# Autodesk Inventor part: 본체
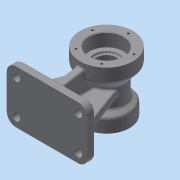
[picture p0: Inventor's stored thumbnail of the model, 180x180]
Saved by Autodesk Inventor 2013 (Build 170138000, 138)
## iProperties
Created: 2015-08
Part Number: 본체
Material: 일반
Document SubType Name: Modeling
Designer: Administrator
Density: 1 g/cm^3
Author: Administrator
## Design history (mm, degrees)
sketch "스케치3"
  geometry: L1 (0, 45)-(0, -45); L2 (0, 45)-(40, 45); L3 (40, 45)-(40, 25); L4 (26, 8.315)-(26, -19.804); L5 (26, -19.804)-(35, -25); L6 (35, -25)-(35, -45); L7 (35, -45)-(0, -45); L8 (26, 8.315)-(40, 25); 2 further points
  constraints: 16 end point, 3 parallel, 2 perpendicular, 1 coincident, 1 midpoint, 1 vertical
  dimensions: "d0" = 90 distance of L1.start L1.end; "d1" = 70 diameter of L6 L1; "d2" = 80 diameter of L3 L1; "d3" = 20 distance of L2.end L3.end; "d4" = 20 distance of L5.end L6.end; "d5" = 60 deg angle of L4 L5; "d6" = 40 deg angle of L4 L8; "d7" = 52 diameter of L4 L1
revolve "회전1" sketch "스케치3" stored, may be unused: angle "d8" = 90 deg
node "작업 평면1"
sketch "스케치8"
  geometry: L1 (61, -40)-(-61, -40); L2 (-61, -40)-(-61, 40); L3 (-61, 40)-(61, 40); L4 (61, 40)-(61, -40); L5 (61, -40)-(-61, 40); L6 (-61, -40)-(61, 40); 1 further point
  constraints: 12 end point, 2 midpoint, 2 parallel, 1 horizontal, 1 perpendicular
  dimensions: "d27" = 122 distance of L2.end L3.end; "d28" = 80 distance of L1.end L2.end
extrude "돌출3" join sketch "스케치8" distance "d29" = 12; taper "d30" = 0 deg
fillet "모깎기2" dims "d31" = 14
sketch "스케치9"
  geometry: L1 (6, -6)-(-6, -6); L2 (-6, -6)-(-6, 6); L3 (-6, 6)-(6, 6); L4 (6, 6)-(6, -6); L5 (6, -6)-(-6, 6); L6 (-6, -6)-(6, 6); 1 further point
  constraints: 12 end point, 2 midpoint, 2 parallel, 1 horizontal, 1 perpendicular
  dimensions: "d32" = 12 distance of L2.end L3.end; "d33" = 12 distance of L1.end L2.end
extrude "돌출4" join sketch "스케치9" stored distance "d34" = 12; taper "d35" = 0 deg
sketch "스케치10"
  geometry: L1 (61, -90)-(-61, -90) reference; L2 (-61, -90)-(-61, -78) reference; L3 (-61, -78)-(-6, -78) reference; L4 (-6, -78)-(-6, -25.298) reference; L5 (6, -25.298)-(6, -78) reference; L6 (6, -78)-(61, -78) reference; L7 (61, -78)-(61, -90) reference; L8 (25.091, -6.815)-(51, -78); A1 r 26 centre (0, 0) between (6, -25.298) and (-6, -25.298) reference; 1 further point
  constraints: 2 end point, 1 point on circle, 1 point on line
  dimensions: "d36" = 10 distance from line of L7 L8.end; "d37" = 70 deg angle of L6 L8
feature "리브2" sketch "스케치10" dims "d38" = 1, "d39" = 12, "d40" = 0, "d41" = 0, "d42" = 1, "d43" = 1
sketch "스케치11"
  geometry: L1 (-40, 45)-(40, 45) reference; L2 (40, 45)-(40, 25) reference; L3 (40, 25)-(26, 8.315) reference; L4 (26, 8.315)-(26, -19.804) reference; L5 (26, -19.804)-(35, -25) reference; L6 (35, -25)-(35, -45) reference; L7 (35, -45)-(-35, -45) reference; L8 (-35, -45)-(-35, -25) reference; L9 (-35, -25)-(-26, -19.804) reference; L10 (-26, -19.804)-(-26, -6) reference; L11 (-26, -6)-(-78, -6) reference; L12 (-78, -6)-(-78, -40) reference; L13 (-78, -40)-(-90, -40) reference; L14 (-90, -40)-(-90, 40) reference; L15 (-90, 40)-(-78, 40) reference; L16 (-78, 40)-(-78, 6) reference; L17 (-78, 6)-(-26, 6) reference; L18 (-26, 6)-(-26, 8.315) reference; L19 (-26, 8.315)-(-40, 25) reference; L20 (-40, 25)-(-40, 45) reference; L21 (-35, -30)-(-78, -30); 1 further point
  constraints: 2 end point, 2 point on line, 1 perpendicular
  dimensions: "d44" = 10 distance from line of L13 L21.end
feature "리브3" sketch "스케치11" dims "d45" = 1, "d46" = 12, "d47" = 0, "d48" = 0, "d49" = 1, "d50" = 1
sketch "스케치12"
  geometry: L1 (-40, 45)-(40, 45) reference; L2 (40, 45)-(40, 25) reference; L3 (40, 25)-(26, 8.315) reference; L4 (26, 8.315)-(26, -19.804) reference; L5 (26, -19.804)-(35, -25) reference; L6 (35, -25)-(35, -45) reference; L7 (35, -45)-(-35, -45) reference; L8 (-35, -45)-(-35, -30) reference; L9 (-35, -30)-(-78, -30) reference; L10 (-78, -30)-(-78, -40) reference; L11 (-78, -40)-(-90, -40) reference; L12 (-90, -40)-(-90, 40) reference; L13 (-90, 40)-(-78, 40) reference; L14 (-78, 40)-(-78, 6) reference; L15 (-78, 6)-(-26, 6) reference; L16 (-26, 6)-(-26, 8.315) reference; L17 (-26, 8.315)-(-40, 25) reference; L18 (-40, 25)-(-40, 45) reference; L19 (-40, 36.7)-(-78, 30); 1 further point
  constraints: 2 end point, 2 point on line
  dimensions: "d51" = 10 distance from line of L19.end L13; "d52" = 80 deg angle of L14 L19
feature "리브4" sketch "스케치12" dims "d53" = 1, "d54" = 12, "d55" = 0, "d56" = 0, "d57" = 1, "d58" = 1
hole "구멍1" diameter "d61" = 38; stored, may be unused: countersink angle "d65" = 90 deg, drill point angle "d67" = 0 deg; dims "d59" = 10, "d60" = 10, "d62" = 6, "d63" = 52, "d64" = 20, "d66" = 23
hole "구멍2" diameter "d70" = 32; stored, may be unused: countersink angle "d74" = 90 deg, drill point angle "d76" = 118 deg; dims "d68" = 10, "d69" = 10, "d71" = 6, "d72" = 40, "d73" = 17, "d75" = 23
sketch "스케치13"
  geometry: C1 r 26 at (0, 0) reference; 1 further point
  constraints: 1 vertical alignment
  dimensions: "d77" = 33 distance of C1.centre point (0, 33)
hole "구멍3" sketch "스케치13" at (0, 33) diameter "d78" = 3.242; stored, may be unused: countersink angle "d82" = 90 deg, drill point angle "d84" = 118 deg; dims "d79" = 10, "d80" = 40, "d81" = 17, "d83" = 13
sketch "스케치14"
  geometry: C1 r 20 at (0, 0) reference; 1 further point
  constraints: 1 vertical alignment
  dimensions: "d88" = 27 distance of C1.centre point (0, 27)
hole "구멍4" sketch "스케치14" at (0, 27) diameter "d89" = 3.242; stored, may be unused: countersink angle "d93" = 90 deg, drill point angle "d95" = 118 deg; dims "d90" = 10, "d91" = 40, "d92" = 17, "d94" = 13
sketch "스케치15"
  geometry: L1 (33, 24)-(33, 18); L2 (21, 24)-(21, 18); L3 (98, -12)-(4, -12) reference; L4 (-10, 0)-(4, 0) reference; L5 (-10, 0)-(0, 0) reference; L6 (0, 0)-(45, 0) reference; L7 (45, 0)-(45, 52.702) reference; L8 (0, 0)-(25.909, 71.185) reference; L9 (-10, -12)-(-10, 0) reference; L10 (112, -12)-(-10, -12) reference; L11 (112, 0)-(112, -12) reference; L12 (102, 0)-(112, 0) reference; L13 (57, 0)-(102, 0) reference; L14 (57, 52.702)-(57, 0) reference; L15 (76.091, 71.185)-(102, 0) reference; C1 r 16 at (51, 78) reference; A1 r 26 centre (51, 78) between (25.909, 71.185) and (45, 52.702) reference; A2 r 6 centre (27, 24) between (33, 24) and (21, 24); A3 r 6 centre (27, 18) between (21, 18) and (33, 18); A4 r 26 centre (51, 78) between (25.909, 71.185) and (45, 52.702) reference; A5 r 26 centre (51, 78) between (57, 52.702) and (76.091, 71.185) reference; A6 r 26 centre (51, 78) between (76.091, 71.185) and (25.909, 71.185) reference
  constraints: 4 end point, 4 point on circle, 4 tangent, 2 centre point, 1 vertical alignment
  dimensions: "d99" = 12 diameter of A2; "d100" = 12 diameter of A3; "d101" = 18 dimension on A3 A2; "d103" = 18 distance from line of A3.centre L4; "d104" = 24 horizontal distance of A1.centre A3.centre
extrude "돌출5" cut sketch "스케치15" stored distance "d105" = 10; taper "d106" = 0 deg
fillet "모깎기3" dims "d107" = 3
fillet "모깎기4" dims "d108" = 5
fillet "모깎기5" dims "d109" = 0.3
fillet "모깎기6" dims "d110" = 3
sketch "스케치16"
  geometry: C1 r 6 at (-47, 26); C2 r 6 at (47, 26); C3 r 6 at (-47, -26); C4 r 6 at (47, -26); A1 r 14 centre (-47, 26) between (-47, 40) and (-61, 26) reference; A2 r 14 centre (-47, -26) between (-61, -26) and (-47, -40) reference; A3 r 14 centre (47, -26) between (47, -40) and (61, -26) reference; A4 r 14 centre (47, 26) between (61, 26) and (47, 40) reference; 1 further point
  constraints: 4 centre point, 4 coincident
  dimensions: "d111" = 12 diameter of C1; "d112" = 12 diameter of C2; "d113" = 12 diameter of C3; "d114" = 12 diameter of C4
extrude "돌출6" cut sketch "스케치16" stored distance "d115" = 10; taper "d116" = 0 deg
fillet "모깎기7" dims "d117" = 3
sketch "스케치17"
  geometry: L1 (35, -15)-(-17, -15) reference; L2 (-28, -3)-(-17, -3) reference; L3 (-21, 37.119)-(-21, 0) reference; 2 further points
  constraints: 1 other
  dimensions: "d119" = 24 distance from line of point (-5, 21) L2; "d120" = 16 distance from line of L3 point (-5, 21)
feature "엠보싱1" sketch "스케치17" dims "d121" = 0.5, "d122" = 0
chamfer "모따기1" distance "d123" = 1; stored, may be unused: second distance "d124" = 2, angle "d125" = 45 deg
node "솔리드1"
mirror "대칭2"
pattern_circular "원형 패턴1" dims angle "d86" = 360 deg
pattern_circular "원형 패턴2" dims angle "d97" = 360 deg
mirror "대칭3"
node "절단 모서리 투영3"
node "절단 모서리 투영4"
node "절단 모서리 투영5"
node "절단 모서리 투영6"
